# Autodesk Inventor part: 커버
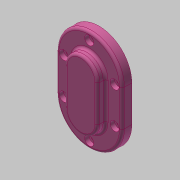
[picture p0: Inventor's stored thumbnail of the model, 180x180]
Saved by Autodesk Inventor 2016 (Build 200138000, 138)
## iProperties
Created: 2019-03
Part Number: 커버
Material: 알루미늄 6061
Document SubType Name: Modeling
Designer: mduedu
Density: 1 g/cm^3
Appearance: 분홍색
Author: mduedu
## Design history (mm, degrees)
sketch "스케치1"
  geometry: L1 (-62, 40)-(62, 40); L2 (62, 40)-(62, -40); L3 (62, -40)-(-62, -40); L4 (-62, -40)-(-62, 40); L5 (-62, 40)-(62, -40); L6 (62, 40)-(-62, -40); 1 further point
  constraints: 12 end point, 2 midpoint, 2 parallel, 1 horizontal, 1 perpendicular
  dimensions: "d59" = 124 distance of L2.end L3.end; "d60" = 80 distance of L1.end L2.end
extrude "돌출1" new body sketch "스케치1" distance "d4" = 12; taper "d5" = 0 deg
fillet "모깎기4"
fillet "모깎기5"
sketch "스케치2"
  geometry: L1 (-20, -22)-(20, -22); L2 (20, -22)-(20, 22); L3 (20, 22)-(-20, 22); L4 (-20, 22)-(-20, -22); L5 (-20, -22)-(20, 22); L6 (20, -22)-(-20, 22); 3 further points
  constraints: 12 end point, 4 midpoint, 2 horizontal alignment, 2 parallel, 1 horizontal, 1 perpendicular, 4 other
  dimensions: "d6" = 40 distance between parallel lines of L2 L4; "d8" = 44 distance between parallel lines of L1 L3
extrude "돌출2" join sketch "스케치2" distance "d9" = 10; taper "d10" = 0 deg
fillet "모깎기2" dims "d12" = 3
sketch "스케치3"
  geometry: L1 (-31, -22)-(31, -22); L2 (31, -22)-(31, 22); L3 (31, 22)-(-31, 22); L4 (-31, 22)-(-31, -22); L5 (-31, -22)-(31, 22); L6 (31, -22)-(-31, 22); A1 r 31 centre (0, 22) between (31, 22) and (0, 53); A2 r 31 centre (0, -22) between (31, -22) and (0, -53); 7 further points
  constraints: 12 end point, 6 midpoint, 4 coincident, 4 point on circle, 2 centre point, 2 parallel, 2 vertical alignment, 1 horizontal, 1 perpendicular
  dimensions: "d76" = 44 distance between parallel lines of L1 L3; "d78" = 62 distance between parallel lines of L2 L4
hole "구멍2" sketch "스케치3" at (0, 53), (31, 22), (31, -22), (-31, -22), (-31, 22), (0, -53) diameter "d28" = 5.5; stored, may be unused: countersink angle "d32" = 90 deg, drill point angle "d34" = 118 deg; dims "d29" = 6, "d30" = 4, "d31" = 2, "d33" = 8
sketch "스케치10"
  geometry: L1 (40, -22)-(40, 22) reference; L2 (-40, 22)-(-40, -22) reference; L3 (23, -22)-(23, 22) reference; L4 (-23, 22)-(-23, -22) reference; C1 r 2.75 at (-31, 22) reference; C2 r 2.75 at (31, -22) reference; C3 r 2.75 at (0, 53) reference; C4 r 2.75 at (31, 22) reference; C5 r 2.75 at (-31, -22) reference; C6 r 2.75 at (0, -53) reference; A1 r 40 centre (0, -22) between (-40, -22) and (40, -22) reference; A2 r 40 centre (0, 22) between (40, 22) and (-40, 22) reference; A3 r 23 centre (0, -22) between (-23, -22) and (23, -22) reference; A4 r 23 centre (0, 22) between (23, 22) and (-23, 22) reference; 7 further points
  constraints: 6 coincident
hole "구멍5" sketch "스케치10" at (0, 53), (31, 22), (31, -22), (0, -53), (-31, -22), (-31, 22) diameter "d79" = 11; stored, may be unused: countersink angle "d83" = 90 deg, drill point angle "d85" = 0 deg; dims "d80" = 6, "d81" = 4, "d82" = 2, "d84" = 5.4
fillet "모깎기3" dims "d68" = 3
sketch "스케치6"
  geometry: C1 r 12.5 at (0, 22); 1 further point
  constraints: 1 centre point, 1 vertical alignment
  dimensions: "d43" = 25 diameter of C1; "d45" = 22 distance of C1.centre point (0, 0)
extrude "돌출5" cut sketch "스케치6" distance "d47" = 15; taper "d48" = 0 deg
node "솔리드1"
mirror "대칭1"
node "투영된 루프5"
